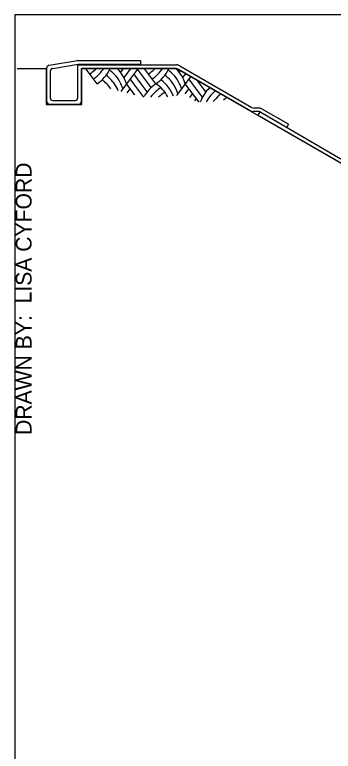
# Model space of a CAD drawing. Extents: x 99862 to 103151, y 100000 to 102076.
# Drawn here: x 99862 to 100184, y 101330 to 102076 of the extents above; entities that cross this region are included whole.
import ezdxf

# ---------------------------------------------------------------- set-up
doc = ezdxf.new("R2010")
doc.units = 0
for name, color, linetype in [('Level 1', 7, 'Continuous'), ('Level 21', 7, 'Continuous'), ('Level 31', 7, 'Continuous'), ('Level 33', 7, 'Continuous'), ('Level 34', 7, 'Continuous'), ('Level 62', 7, 'Continuous')]:
    doc.layers.add(name, color=color, linetype=linetype)

msp = doc.modelspace()

# ---------------------------------------------------------------- linework, layer by layer
at = {"layer": 'Level 1'}
msp.add_lwpolyline([(99862, 99999.5), (103151, 99999.5), (103151, 102075.5), (99862, 102075.5)], close=True, dxfattribs=at)
at = {"layer": 'Level 21'}
for p, q in [((99945.29, 102005.62), (99934.14, 102020.49)), ((99971.29, 102020.49), (99968.87, 102017.26)), ((99978.72, 102020.49), (99972.32, 102011.95)), ((99986.14, 102020.49), (99974.99, 102005.62)), ((99989.84, 102005.62), (99982.41, 102015.52)), ((99997.26, 102005.62), (99986.13, 102020.47)), ((100004.69, 102005.62), (99993.53, 102020.49)), ((100029.3, 102018.63), (100028.27, 102017.26)), ((100034.48, 102015.64), (100031.71, 102011.95)), ((99982.41, 102005.62), (99978.7, 102010.57)), ((100039.66, 102012.66), (100034.39, 102005.62)), ((100041.81, 102005.62), (100038.1, 102010.57)), ((100049.24, 102005.62), (100047.23, 102008.29)), ((99974.99, 102005.62), (99969.19, 101997.89)), ((99983.3, 101994.54), (99974.99, 102005.62)), ((99978.7, 102000.67), (99975.46, 101996.35)), ((99992.51, 101992.16), (99982.41, 102005.62)), ((99995.96, 101997.46), (99989.84, 102005.62)), ((100000.03, 102001.93), (99997.26, 102005.62)), ((100034.39, 102005.62), (100025.47, 101993.73)), ((100038.1, 102000.67), (100034.04, 101995.27)), ((100048.46, 101986.86), (100034.39, 102005.62)), ((100051.91, 101992.16), (100041.81, 102005.62)), ((100055.35, 101997.46), (100049.24, 102005.62)), ((99982.41, 101995.72), (99981.79, 101994.88)), ((100041.81, 101995.72), (100038.68, 101991.55)), ((100045.52, 101990.77), (100043.69, 101988.33))]:
    msp.add_line(p, q, dxfattribs=at)
for centre, start, end in [((99913.19, 102051.66), 303.90361, 303.96414), ((99916.91, 102046.71), 303.90361, 315.75995), ((99920.62, 102041.76), 303.90361, 311.04014), ((99920.62, 102041.76), 311.04008, 325.53208), ((99924.33, 102036.81), 303.90361, 334.26411), ((99931.76, 101984.33), 34.50891, 52.8994), ((99935.47, 101989.28), 25.7734, 53.69375), ((99939.18, 101994.23), 17.6434, 44.33446), ((99972.59, 102051.66), 303.90361, 303.96414), ((99976.3, 102046.71), 303.90361, 315.75995), ((99980.02, 102041.76), 303.90361, 311.04014), ((99980.02, 102041.76), 311.04008, 325.53208), ((99983.73, 102036.81), 303.90361, 334.26411), ((99991.15, 101984.33), 34.50891, 52.8994), ((99994.86, 101989.28), 25.7734, 53.69375), ((99998.58, 101994.23), 17.6434, 44.33446), ((99928.04, 101979.38), 44.28722, 53.669), ((99987.44, 101979.38), 44.28722, 53.669), ((99928.04, 101979.38), 34.2015, 44.28731), ((99931.76, 101984.33), 22.24578, 34.50898), ((99935.47, 101989.28), 17.6434, 25.77346), ((100025.65, 101974.43), 123.90366, 150.73452), ((99983.73, 101974.43), 28.77332, 56.09639), ((100029.36, 101969.48), 121.45354, 131.04032), ((99987.44, 101979.38), 21.64213, 44.28731), ((99991.15, 101984.33), 17.6434, 34.50898), ((99994.86, 101989.28), 17.6434, 25.77346), ((100085.05, 101974.43), 133.89454, 160.72538), ((100029.36, 101969.48), 131.04025, 142.86294), ((100033.07, 101964.53), 120.69785, 133.08239), ((100088.76, 101969.48), 131.04025, 152.34112), ((100088.76, 101969.48), 129.98985, 131.04032), ((100092.47, 101964.53), 125.98532, 139.05866), ((100096.18, 101959.58), 121.85152, 128.29271), ((100092.47, 101964.53), 139.05859, 142.31218)]:
    msp.add_arc(centre, 37.58, start, end, dxfattribs=at)
at = {"layer": 'Level 31'}
for p, q in [((99893.85, 102020.68), (99864.43, 102020.68)), ((99893.85, 102020.68), (99893.85, 101984.68)), ((99929.85, 101984.68), (99929.85, 102020.68)), ((100026.1, 102020.68), (99929.85, 102020.68)), ((100026.1, 102020.68), (100318.15, 101852.29)), ((99893.85, 101984.68), (99929.85, 101984.68)), ((100104.65, 101975.49), (100104.65, 101975.49))]:
    msp.add_line(p, q, dxfattribs=at)
at = {"layer": 'Level 33'}
for p, q in [((99896.65, 102024.27), (99925.4, 102029.13)), ((99925.9, 102029.18), (99989.23, 102029.18)), ((99989.23, 102029.18), (99989.23, 102025.43)), ((99894.15, 102021.31), (99894.15, 101987.98)), ((99900.4, 102021.1), (99925.96, 102025.43)), ((99925.8, 101991.23), (99925.8, 102024.71)), ((99925.96, 102025.43), (99989.23, 102025.43)), ((99929.55, 101987.98), (99929.55, 102020.96)), ((99897.9, 102018.14), (99897.9, 101991.23)), ((99897.15, 101984.98), (99926.55, 101984.98)), ((99900.4, 101988.73), (99923.3, 101988.73)), ((100108.22, 101977.53), (100102.88, 101977.53)), ((100108.83, 101981.04), (100104.3, 101981.04)), ((100138.65, 101964.6), (100111.33, 101980.37))]:
    msp.add_line(p, q, dxfattribs=at)
for points in [[(99925.8, 102024.71), (99989.23, 102024.71)], [(99925.8, 102024.71), (99989.23, 102024.71)], [(100024.65, 102020.96), (99929.55, 102020.96)], [(99989.24, 102024.71), (100025.65, 102024.71)], [(100028.78, 102023.87), (100101.8, 101981.71)], [(100100.38, 101978.2), (100027.77, 102020.12)], [(100138.65, 101964.6), (100136.98, 101961.7)]]:
    msp.add_lwpolyline(points, dxfattribs=at)
for centre, radius, start, end in [((99925.9, 102026.18), 3, 90, 99.60607), ((99897.15, 102021.31), 3, 99.60607, 180), ((99900.9, 102018.14), 3, 99.60607, 180), ((100024.65, 102014.71), 6.25, 75, 90), ((100025.65, 102018.46), 6.25, 60, 90), ((100024.65, 102014.71), 6.25, 60, 75), ((99900.4, 101991.23), 2.5, 180, 270), ((99923.3, 101991.23), 2.5, 270, 360), ((99897.15, 101987.98), 3, 180, 270), ((99926.55, 101987.98), 3, 270, 0), ((100102.88, 101982.53), 5, 240, 270), ((100104.3, 101986.04), 5, 240, 270), ((100107.7, 101982.53), 5, 270, 270.00041), ((100108.22, 101972.53), 5, 60, 90.00041), ((100108.83, 101976.04), 5, 60, 90)]:
    msp.add_arc(centre, radius, start, end, dxfattribs=at)
at = {"layer": 'Level 34'}
for points in [[(100109.71, 101977.14), (100107.84, 101973.89)], [(100110.72, 101976.86), (100231.58, 101906.32)], [(100228.45, 101904.37), (100107.84, 101973.89)]]:
    msp.add_lwpolyline(points, dxfattribs=at)

# ---------------------------------------------------------------- texts
at = {"layer": 'Level 62'}
msp.add_text('DRAWN BY:  LISA CYFORD', height=16, rotation=90, dxfattribs=at).set_placement((99879, 101650.01))

doc.saveas('drawing.dxf')
